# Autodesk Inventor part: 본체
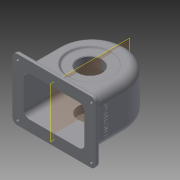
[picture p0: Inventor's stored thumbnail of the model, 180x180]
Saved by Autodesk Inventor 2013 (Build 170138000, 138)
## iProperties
Created: 2016-01
Part Number: 본체
Material: 일반
Document SubType Name: Modeling
Designer: dgall
Density: 1 g/cm^3
Author: dgall
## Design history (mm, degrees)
sketch "스케치1"
  geometry: L1 (-57, 0)-(-57, -64); L2 (57, 0)-(57, -64); L3 (57, -64)-(-57, -64); A1 r 57 centre (0, 0) between (57, 0) and (-57, 0); 1 further point
  constraints: 6 end point, 2 point on circle, 2 tangent, 1 centre point, 1 coincident, 1 parallel, 1 perpendicular, 1 vertical
  dimensions: "d0" = 114 diameter of A1; "d2" = 64 distance of L1.start L1.end
extrude "돌출1" new body sketch "스케치1" stored distance "d3" = 77; taper "d4" = 0 deg
node "작업 평면1"
sketch "스케치2"
  geometry: L1 (57, 0)-(57, -64) reference; L2 (57, -64)-(-57, -64) reference; L3 (-57, -64)-(-57, 0) reference; L4 (-51, 0)-(-51, -64); L5 (51, 0)-(51, -64); A1 r 57 centre (0, 0) between (57, 0) and (-57, 0) reference; A2 r 51 centre (0, 0) between (51, 0) and (-51, 0); 1 further point
  constraints: 4 end point, 2 perpendicular, 2 point on circle, 2 point on line, 2 tangent, 1 centre point, 1 coincident
  dimensions: "d5" = 102 diameter of A2
extrude "돌출2" cut sketch "스케치2" stored distance "d7" = 67; taper "d8" = 0 deg
node "작업 평면2"
sketch "스케치3"
  geometry: L1 (114, 0)-(114, -77) reference; L2 (0, 0)-(114, 0) reference; L3 (0, 0)-(0, -77) reference; L4 (114, -77)-(0, -77) reference; L5 (-13, -90.5)-(127, -90.5); L6 (127, -90.5)-(127, 13.5); L7 (127, 13.5)-(-13, 13.5); L8 (-13, 13.5)-(-13, -90.5); 1 further point
  constraints: 8 end point, 2 parallel, 1 horizontal, 1 perpendicular
  dimensions: "d9" = 70 distance from line of point (57, -38.5) L6; "d10" = 140 distance of L6.end L7.end; "d11" = 52 distance from line of point (57, -38.5) L7; "d12" = 104 distance of L7.end L5.start
extrude "돌출3" join sketch "스케치3" distance "d13" = 7; taper "d14" = 0 deg
node "작업 평면3"
sketch "스케치4"
  geometry: C1 r 6 at (0, 0); 1 further point
  constraints: 1 centre point, 1 coincident
  dimensions: "d16" = 12 diameter of C1
extrude "돌출4" join sketch "스케치4" stored distance "d18" = 7; taper "d19" = 0 deg
sketch "스케치5"
  geometry: L1 (77, 121)-(0, 121) reference; L2 (-13.5, 0)-(90.5, 0) reference; L3 (0, 121)-(0, 0); L4 (0, 60.5)-(58.757, 60.5); L5 (72, 64)-(72, 115) reference; L6 (72, 0)-(72, 64) reference; L7 (77, 7)-(77, 64) reference; L8 (77, 64)-(77, 121) reference; L9 (5, 64)-(5, 0) reference; L10 (5, 115)-(5, 64) reference; L11 (5, 100.247)-(19, 88.5); L12 (19, 88.5)-(19, 60.5); L13 (19, 60.5)-(5, 60.5); L14 (5, 100.247)-(5, 60.5); 1 further point
  constraints: 12 end point, 5 point on line, 3 perpendicular, 1 collinear, 1 midpoint, 1 parallel
  dimensions: "d20" = 50 deg angle of L12 L11; "d21" = 56 diameter of L11.end L4; "d23" = 19 distance between parallel lines of L3 L12
revolve "회전1" sketch "스케치5" stored, may be unused: angle "d24" = 90 deg
sketch "스케치6"
  geometry: L1 (19, 32.5)-(19, 88.5) reference; L2 (5, 100.247)-(19, 88.5) reference; L3 (5, 20.753)-(19, 32.5) reference; L4 (19, 60.5)-(-7.161, 60.5); L5 (0, 121)-(0, 64) reference; L6 (0, 64)-(0, 7) reference; L7 (0, 97.916)-(3, 95.399); L8 (3, 95.399)-(3, 60.5); L9 (0, 97.916)-(0, 60.5); L10 (3, 60.5)-(0, 60.5); 1 further point
  constraints: 10 end point, 4 point on line, 2 parallel, 2 perpendicular, 1 midpoint
  dimensions: "d25" = 5 distance between parallel lines of L2 L7; "d28" = 3 distance between parallel lines of L5 L8
revolve "회전2" sketch "스케치6" stored, may be unused: angle "d29" = 90 deg
sketch "스케치7"
  geometry: C1 r 34.899 at (0, 0) reference; C2 r 20 at (0, 0); 1 further point
  constraints: 1 centre point, 1 coincident
  dimensions: "d30" = 40 diameter of C2
extrude "돌출5" cut sketch "스케치7" stored distance "d32" = 7; taper "d33" = 0 deg
sketch "스케치8"
  geometry: L1 (72, 40.5)-(72, 80.5) reference; L2 (72, 80.5)-(77, 80.5) reference; L3 (72, 40.5)-(77, 40.5) reference; L4 (72, 60.5)-(100.994, 60.5); L5 (77, 64)-(77, 121) reference; L6 (77, 7)-(77, 64) reference; L7 (77, 91.5)-(87, 91.5); L8 (87, 91.5)-(87, 80.5); L9 (87, 80.5)-(77, 80.5); L10 (0, 121)-(0, 64) reference; L11 (77, 91.5)-(77, 80.5); 1 further point
  constraints: 10 end point, 2 parallel, 2 perpendicular, 1 collinear, 1 midpoint, 1 point on line
  dimensions: "d37" = 87 distance between parallel lines of L10 L8; "d38" = 62 diameter of L7 L4
revolve "회전3" sketch "스케치8" stored, may be unused: angle "d39" = 90 deg
sketch "스케치9"
  geometry: L1 (90.5, -64)-(-13.5, -64) reference; L2 (38.5, -64)-(38.5, -34); L3 (14.636, -30.623)-(62.364, -30.623); L4 (62.364, -30.623)-(62.364, -37.377); L5 (62.364, -37.377)-(14.636, -37.377); L6 (14.636, -37.377)-(14.636, -30.623); L7 (14.636, -34)-(62.364, -34); L8 (38.5, -30.623)-(38.5, -37.377); 1 further point
  constraints: 6 end point, 5 midpoint, 1 perpendicular, 2 other
  dimensions: "d40" = 30 distance of L2.start L2.end; "d42" = 0 distance between parallel lines of L2 L8; "d43" = 0 distance from line of L2.end L7
extrude "돌출6" join sketch "스케치9" distance "d44" = 0.5; taper "d45" = 0 deg
fillet "모깎기1" dims "d46" = 14
fillet "모깎기2" dims "d47" = 9
chamfer "모따기1" distance "d48" = 1; stored, may be unused: second distance "d49" = 2, angle "d50" = 45 deg
fillet "모깎기3" dims "d51" = 1
fillet "모깎기4" dims "d52" = 8
sketch "스케치10"
  geometry: C1 r 2.5 at (-5, 82.5); C2 r 2.5 at (-5, -5.5); C3 r 2.5 at (119, -5.5); C4 r 2.5 at (119, 82.5); A1 r 8 centre (-5, 82.5) between (-5, 90.5) and (-13, 82.5) reference; A2 r 8 centre (-5, -5.5) between (-13, -5.5) and (-5, -13.5) reference; A3 r 8 centre (119, -5.5) between (119, -13.5) and (127, -5.5) reference; A4 r 8 centre (119, 82.5) between (127, 82.5) and (119, 90.5) reference; 1 further point
  constraints: 4 centre point, 4 coincident
  dimensions: "d53" = 5 diameter of C1; "d55" = 5 diameter of C4; "d56" = 5 diameter of C3; "d57" = 5 diameter of C2
extrude "돌출7" cut sketch "스케치10" stored distance "d58" = 0.5; taper "d59" = 0 deg
fillet "모깎기5" dims "d60" = 3
fillet "모깎기6" dims "d61" = 3
fillet "모깎기7" dims "d62" = 3
fillet "모깎기8" dims "d63" = 3
node "솔리드1"
node "투영된 루프1"
other parameters: "d15" = 63
